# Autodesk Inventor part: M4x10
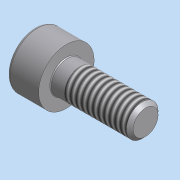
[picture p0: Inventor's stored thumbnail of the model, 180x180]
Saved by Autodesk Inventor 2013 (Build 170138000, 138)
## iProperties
Company: 한국ATC센터
Created: 2015-05
Part Number: M4x10
Document SubType Name: 모델링
Designer: KYOUNG IL JANG
Vendor: CBT Solutions
Material: 일반
Author: KYOUNG IL JANG
Comments: 파생
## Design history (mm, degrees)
node "KS B 1003 - 미터 M 4 x 10" dims "d0" = 10
node "솔리드1"
node "솔리드 본체"
node "곡면 본체"
feature "Solid1::KS B 1003 - 미터 M 4 x 10" dims "d0" = 10
tag "피쳐 태그1"
